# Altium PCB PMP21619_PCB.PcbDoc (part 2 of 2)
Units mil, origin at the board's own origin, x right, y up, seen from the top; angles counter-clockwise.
Board outline 3937.01 x 3937.01 mil, 8 copper layers (Top Layer, Signal Layer 1, Signal Layer 2, Signal Layer 3, Signal Layer 4, Signal Layer 5, Signal Layer 6, Bottom Layer), stack 62.283 mil thick; 227 components, 41 nets, 547 pads, 421 vias.
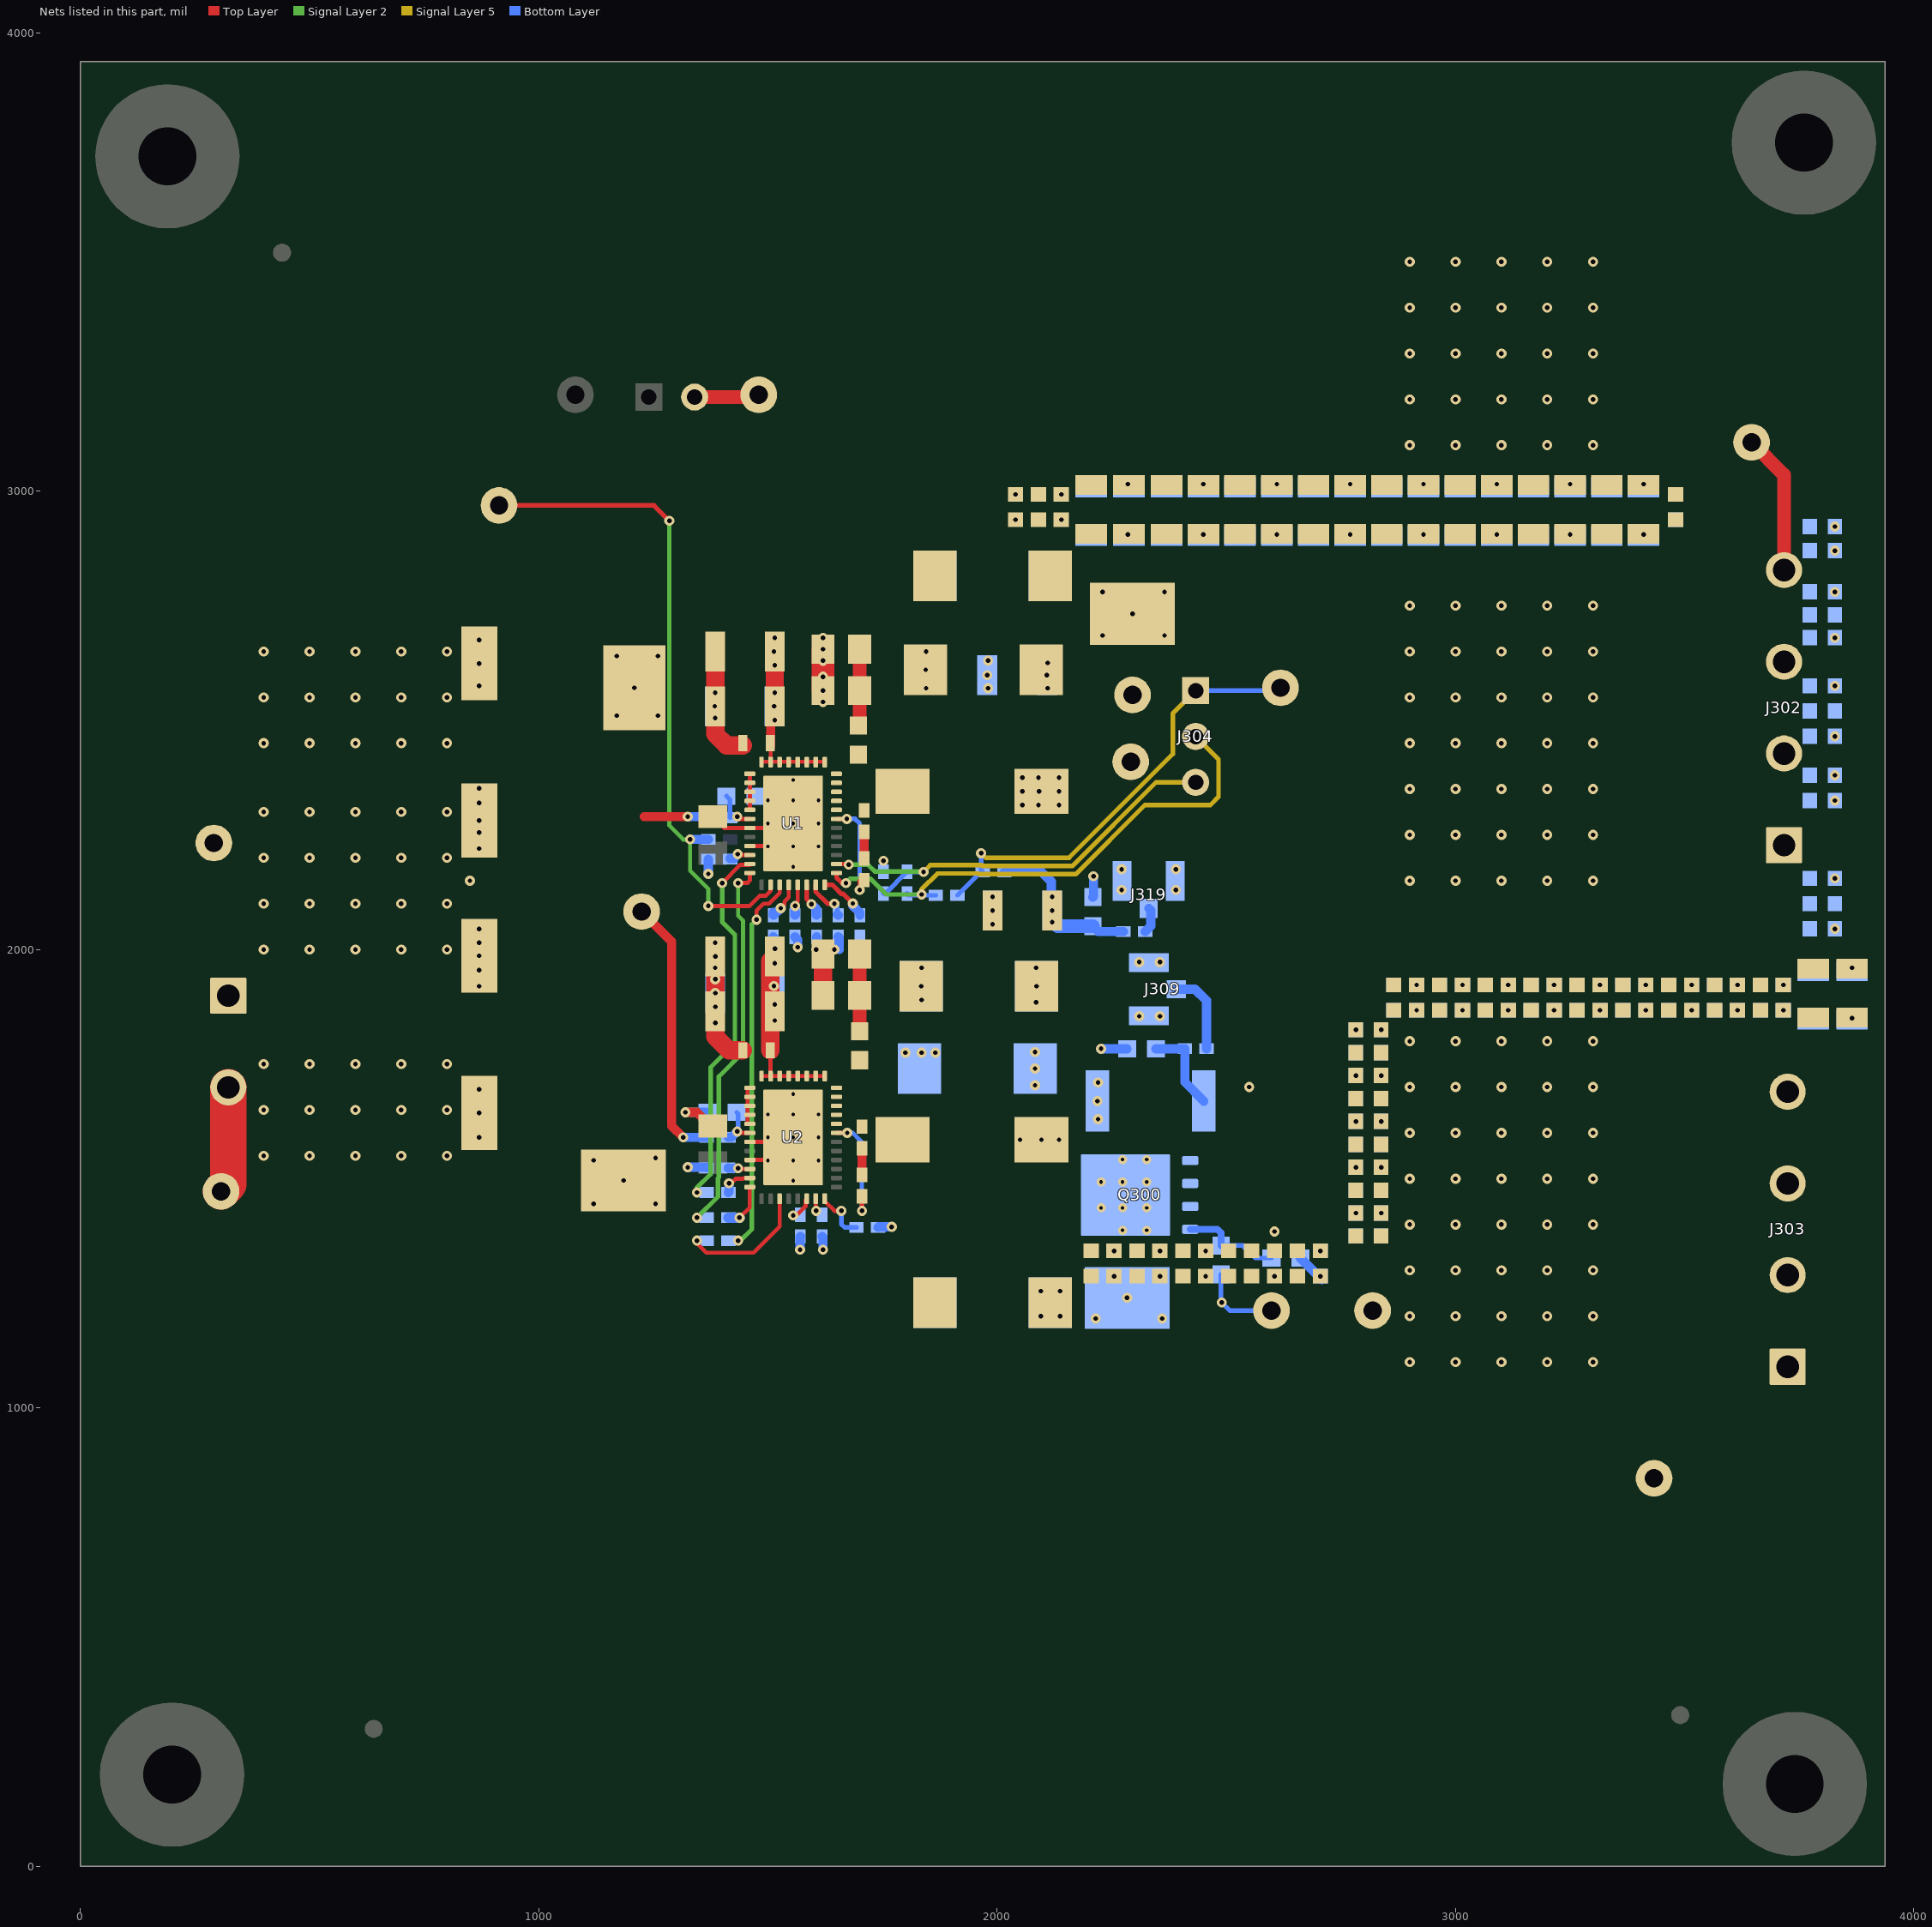
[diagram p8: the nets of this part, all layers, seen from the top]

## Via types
v1: diameter 22, hole 10, Top Layer to Bottom Layer, tented both sides, 317 vias
v2: diameter 22, hole 10, Top Layer to Bottom Layer, 72 vias
v3: diameter 19.68, hole 7.87, Top Layer to Bottom Layer, 32 vias

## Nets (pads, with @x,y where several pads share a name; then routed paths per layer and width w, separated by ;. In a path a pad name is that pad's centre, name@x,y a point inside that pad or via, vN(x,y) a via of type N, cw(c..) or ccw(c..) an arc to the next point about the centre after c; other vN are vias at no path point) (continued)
GND: C10.1 C13.2 C14.1 C15.1 C16.1 C17.1 C20.2 C23.2 C24.2 C25.2 C26.2 C27.2 C50.2 C51.2 C52.2 C53.2 C54.2 C55.2 C56.2 C91.2 C92.2 C93.2 C94.2 C100.2 C101.2 C102.2 C103.2 C104.2 C105.2 C106.2 C107.2 C108.2 C109.2 C110.2 C111.2 C112.2 C113.2 C114.2 C115.2 C116.2 C117.2 C118.2 C119.2 C120.2 C121.2 C122.2 C123.2 C124.2 C125.2 C126.2 C127.2 C128.2 C129.2 C130.2 C131.2 C132.2 C133.2 C134.2 C135.2 C136.2 C137.2 C201.2 C202.2 C203.2 C204.2 C205.2 C206.2 C207.2 C208.2 C209.2 C210.2 C211.2 C212.2 C213.2 C214.2 C215.2 C216.2 C217.2 C218.2 C219.2 C220.2 C221.2 C222.2 C223.2 C224.2 C225.2 C226.2 C227.2 C228.2 C229.2 C230.2 C231.2 C232.2 C233.2 C234.2 C235.2 C236.2 C237.2 C238.2 C239.2 C240.2 C241.2 C242.2 C243.2 C244.2 C245.2 C246.2 C247.2 C248.2 C249.2 C250.2 C251.2 C252.2 C253.2 C254.2 C255.2 C256.2 C257.2 C258.2 C259.2 C260.2 C261.2 C262.2 C263.2 C264.2 C265.2 C266.2 C267.2 C268.2 C269.2 C270.2 C271.2 C272.2 C273.2 C274.2 C275.2 C276.2 C277.2 C278.2 C279.2 C280.2 C281.2 C282.2 C283.2 C284.2 C285.2 C286.2 C300.2 C319.2 J101.2 J300.2 J303.1 J303.2 J303.3 J303.4 J309.2@2330.71,1971.46 J309.3@2330.71,1855.31 J319.2@2388.78,2149.61 J319.3@2272.64,2149.61 R10.1 R11.1 R12.1 R13.2 R14.2 R15.2 R16.1 R17.1 R21.1 R23.1 R24.1 R25.2 R26.1 R27.2 R50.1 R302.1 R303.1 TP109.1 TP303.1 TP304.1 TP305.1 TP307.1 TP308.1 TP309.1 TP315.1 U1.13 U1.14 U1.15 U1.16 U1.17 U1.18 U1.19 U1.20 U1.27 U1.29 U1.41@1555,2275 U2.13 U2.14 U2.15 U2.16 U2.17 U2.18 U2.19 U2.20 U2.27 U2.29 U2.41@1555,1590 | length 2405.9
  Top Layer w9: C10.1@1381.89,2288.03 1404.76,2265.16 U1.27@1460.51,2265.16 U1.41@1545.16,2265.16 ; U2.29@1460.51,1540.79 1505.79,1540.79 U2.41@1545.16,1580.16 ; U2.27@1460.51,1580.16 U2.41@1545.16,1580.16 ; U1.29@1460.51,2225.79 1505.79,2225.79 U1.41@1545.16,2265.16 ; U2.20@1486.1,1723.86 U2.19@1505.79,1723.86 ; U1.20@1486.22,2409.45 U1.19@1505.91,2409.45 ; C27.2@1505,1780 1505.79,1779.21 U2.19@1505.79,1723.86 ; C17.1@1505,2445 1505.91,2444.09 U1.19@1505.91,2409.45 ; v3(1555,1590) U2.41@1545.16,1580.16 ; v3(1555,2275) U1.41@1545.16,2265.16 ; U2.13@1623.9,1723.86 U2.19@1505.79,1723.86 ; U1.13@1624.02,2409.45 U1.19@1505.91,2409.45
  Top Layer w20: v1(1320,1645) 1345,1645 1375,1615 C20.2@1385,1615 ; C17.1@1505.91,2445 C16.1@1505.91,2530
  Top Layer w30: J101.2@1340,3205 1475,3205 TP109.1@1480,3210
  Top Layer w40: C27.2@1505,1780 1505,1975.04 C24.2@1514.96,1985 ; C26.2@1509.84,1874.02 C26.2@1513.78,1870.08 ; C16.1@1514.96,2530 C15.1@1514.96,2650 ; R27.2@1620,1900 R26.1@1620,1990
  Top Layer w50: v1(1620,2565) v1(1620,2655)
  Top Layer w80: TP303.1@307.09,1472.44 322.83,1488.19 J300.2@322.83,1699.21
  Bottom Layer w20: v1(1320,1645) C23.2@1368.5,1645 ; v1(1325,1525) 1364.76,1525 R21.1@1366.14,1523.62 ; v1(1370,2165) 1370,2196.77 R13.2@1370.08,2196.85 ; R14.2@1511.61,2027.56 1515.24,2023.94 v1(1515.24,2001.97) ; R12.1@1558.86,2027.56 1565,2021.42 v1(1565,2005) ; v1(1570,1345) 1570,1373.15 R23.1@1570.87,1374.02 ; v1(1605.24,2000) 1606.1,2000.87 R11.1@1606.1,2027.56 ; R24.1@1618.11,1374.02 1620,1372.13 v1(1620,1345) ; R10.1@1653.35,2027.56 1655.24,2025.67 v1@1655.24,2000 ; R25.2@1740.16,1393.7 1741.46,1395 v1(1770,1395) ; C319.2@2208.66,2114.17 2210,2115.51 v1(2210,2160) ; v1(2226.54,1783.46) C300.2@2283.46,1783.46 ; R302.1@2661.42,1326.77 2708.19,1280 2705,1283.19 v1(2705,1287.44)
  other v1: 2900,1100 3000,1100 3100,1100 3200,1100 3300,1100 2215,1195 2360,1195 2900,1200 3000,1200 3100,1200 3200,1200 3300,1200 2283.46,1240.16 2355,1287.44 2900,1300 3000,1300 3100,1300 3200,1300 3300,1300 2900,1400 3000,1400 3100,1400 3200,1400 3300,1400 1120,1445 1255,1445 1185.04,1496.06 2900,1500 3000,1500 3100,1500 3200,1500 3300,1500 1120,1540 1255,1545 400,1550 500,1550 600,1550 700,1550 800,1550 870,1590 2900,1600 3000,1600 3100,1600 3200,1600 3300,1600 2220,1630 870.08,1643.7 400,1650 500,1650 600,1650 700,1650 800,1650 2218.5,1669.29 870,1695 2900,1700 3000,1700 3100,1700 3200,1700 3300,1700 2220,1710 400,1750 500,1750 600,1750 700,1750 800,1750 1800,1775 1835,1775 1865,1775 2900,1800 3000,1800 3100,1800 3200,1800 3300,1800 1515,1845 2310,1854.33 2355,1854.33 1515,1880 1835,1890 1512.99,1920.12 1834.02,1920 1835,1960 1515,1970 2310,1972.44 2355,1972.44 1645,2000 1990,2055 1990.04,2085 1990,2115 2271.65,2130 2390,2130 2271.65,2175 2389.76,2175 1751.97,2193.67 400,2450 500,2450 600,2450 700,2450 800,2450 1515,2500 1170,2510 1260,2510 1513.78,2530.49 1620,2540 400,2550 500,2550 600,2550 700,2550 800,2550 1514.96,2560 1845,2570 1980,2570 1208.66,2570.87 870,2575 1620,2595 1978.35,2598.43 1844.02,2610 1515,2620 870.08,2624.02 1620,2630 1980,2630 1170,2640 1260,2640 400,2650 500,2650 600,2650 700,2650 800,2650 1512.99,2650 1845,2650 870,2675 1515,2680 1620,2680 2230,2685 2365,2685 2295.28,2732.28 2230,2780 2365,2780 2900,3100 3000,3100 3100,3100 3200,3100 3300,3100 2900,3200 3000,3200 3100,3200 3200,3200 3300,3200 2900,3300 3000,3300 3100,3300 3200,3300 3300,3300 2900,3400 3000,3400 3100,3400 3200,3400 3300,3400 2900,3500 3000,3500 3100,3500 3200,3500 3300,3500
  other v2: 2255,1287.44 2455,1287.44 2605,1287.44 2837.56,1425 2837.56,1525 2837.56,1625 2837.56,1725 2837.56,1825 3865,1850 2915,1867.44 3015,1867.44 3115,1867.44 3215,1867.44 3315,1867.44 3415,1867.44 3515,1867.44 3615,1867.44 3715,1867.44 3827.56,2045 3827.56,2155 3827.56,2325 3827.56,2380 3827.56,2465 3827.56,2575 3827.56,2680 3827.56,2780 3827.56,2870 3827.56,2922.64 2040,2992.56 2140,2992.56 2285,3015 2450,3015 2610,3015 2770,3015 2930,3015 3090,3015 3250,3015 3410,3015
  other v3: 1555,1495.51 1499.88,1539.61 1555,1539.61 1610.12,1539.61 1499.88,1590 1610.12,1590 1499.88,1640.39 1555,1640.39 1610.12,1640.39 1555,1684.49 1555,2180.51 1499.88,2224.61 1555,2224.61 1610.12,2224.61 1499.88,2275 1610.12,2275 1499.88,2325.39 1555,2325.39 1610.12,2325.39 1555,2369.49
NetC11_1: C11.1 C12.2 L1.1 U1.8 U1.9 U1.10 U1.11 U1.12
NetC11_2: C11.2 R16.2 R17.2 | length 168.1
  Top Layer w30: C11.2@1696.85,2488.19 1700,2491.34 R17.2@1700,2565 R16.2@1700,2655
NetC12_1: C12.1 R19.1 | length 57.8
  Top Layer w20: R19.1@1710,2198.62 C12.1@1710,2256.38
NetC13_1: C13.1 R31.2 U1.26 | length 94.8
  Top Layer w9: v1@1435,2285 1435.16,2284.84 U1.26@1460.51,2284.84
  Bottom Layer w10: C13.1@1409.45,2334.65 1417.32,2326.77 R31.2@1417.32,2287.4 1419.92,2290 v1(1433,2290) v1@1435,2290
NetC21_1: C21.1 C22.2 L2.1 U2.8 U2.9 U2.10 U2.11 U2.12
NetC21_2: C21.2 R26.2 R27.1 | length 143.5
  Top Layer w30: C21.2@1700,1821.5 R26.2@1700,1965
NetC22_1: C22.1 R29.1 | length 57.8
  Top Layer w20: R29.1@1705,1508.62 C22.1@1705,1566.38
NetC23_1: C23.1 R41.1 U2.26 | length 100
  Top Layer w9: v1(1433,1603) 1436.16,1599.84 U2.26@1460.51,1599.84
  Bottom Layer w10: C23.1@1431.5,1645 1435,1641.5 v1@1435,1600
  Bottom Layer w20: R41.1@1413.62,1590 1420,1590 v1(1433,1603)
NetC300_1: C300.1 Q300.1 Q300.2 Q300.3 R303.2 R304.1 | length 194.3
  Bottom Layer w20: C300.1@2346.46,1783.46 R304.1@2409.45,1783.46 2409.45,1710.63 R303.2@2450.79,1669.29
NetJ304_1: J304.1 R52.1 R53.2 TP107.1 | length 981
  Signal Layer 5 w10: v1(1965,2210) 1975,2200 2156.66,2200 2383.07,2426.41 2383.07,2514.57 J304.1@2433.07,2564.57
  Bottom Layer w10: R52.1@1913.39,2118.11 1964.57,2169.29 R53.2@1968.5,2169.29 1965,2172.8 v1(1965,2210) ; J304.1@2433.07,2564.57 2611.81,2564.57 TP107.1@2618.11,2570.87
NetJ304_2: J304.2 R51.2 R52.2 U1.1 | length 1179.1
  Top Layer w10: U1.1@1649.49,2166.73 1649.49,2156.81 1661.3,2145 v1(1670,2145)
  Signal Layer 2 w10: v1(1670,2145) 1678.87,2153.87 1690.11,2153.87 1724.08,2153.87 1757.95,2120 v1(1835,2120)
  Signal Layer 5 w10: v1(1835,2120) 1835,2131 1870,2166 1958.44,2166 1960.19,2164.25 2171.47,2164.25 2322.22,2315 2465,2315 2483.07,2333.07 2483.07,2414.57 J304.2@2433.07,2464.57
  Bottom Layer w10: R51.2@1803.15,2122.05 1807.09,2118.11 R52.2@1866.14,2118.11
NetJ304_3: J304.3 R50.2 R51.1 U1.2 | length 979.3
  Top Layer w10: U1.2@1649.49,2186.42 v1@1676,2186.42
  Signal Layer 2 w10: v1(1676,2185) 1718.23,2185 1733.44,2169.8 1838.79,2169.8 v1(1839.29,2169.29) ; J304.3@2427.46,2364.57 J304.3@2433.07,2364.57
  Signal Layer 5 w10: v1(1839.29,2169.29) 1853.87,2183.87 1965.85,2183.87 1967.6,2182.13 2164.07,2182.13 2346.51,2364.57 J304.3@2427.46,2364.57
  Bottom Layer w10: R50.2@1751.97,2122.05 1755.91,2122.05 R51.1@1803.15,2169.29 v1(1839.29,2169.29)
NetJ309_1: J309.1 R304.2 | length 181.2
  Bottom Layer w20: J309.1@2390.75,1913.39 2431.61,1913.39 2456.69,1888.31 R304.2@2456.69,1783.46
NetJ319_1: J319.1 R314.1 | length 57
  Bottom Layer w20: R314.1@2322.83,2039.37 2335,2051.54 2335,2085.28 J319.1@2330.71,2089.57
NetQ300_4: Q300.4 R301.1 R302.2 | length 219.5
  Bottom Layer w10: R301.1@2488.19,1354.33 2535.67,1354.33 2563.23,1326.77 R302.2@2598.43,1326.77
  Bottom Layer w15: Q300.4@2421.06,1389.57 2480.43,1389.57 2488.19,1381.81 R301.1@2488.19,1354.33
NetR10_2: R10.2 U1.39 | length 90.5
  Top Layer w10: U1.39@1604.21,2141.14 1604.21,2125.79 1630,2100 v1@1640,2100
  Bottom Layer w10: v1(1645,2100) 1651.48,2093.52 R10.2@1651.48,2076.67
  Bottom Layer w20: R10.2@1651.48,2076.67 R10.2@1653.35,2074.8
NetR11_2: R11.2 U1.38 | length 81.8
  Top Layer w10: U1.38@1584.53,2141.14 1584.53,2109.65 v1(1595,2099.18)
  Bottom Layer w20: v1(1595,2099.18) 1606.1,2088.08 R11.2@1606.1,2074.8 1605.24,2075.67 R11.2@1605.24,2080.94
NetR12_2: R12.2 U1.37 | length 74.5
  Top Layer w9: v1(1559.12,2095) 1559.12,2099.18 1564.84,2104.9 U1.37@1564.84,2141.14
  Bottom Layer w20: v1@1558.86,2095 R12.2@1558.86,2074.8 1560.24,2076.18 R12.2@1560.24,2080.06
NetR13_1: R13.1 U1.30 | length 57.1
  Top Layer w9: v1@1436.1,2206.1 U1.30@1460.51,2206.1
  Bottom Layer w9: R13.1@1417.32,2196.85 1424.95,2196.85 1426.6,2198.5 v1@1436.1,2208
  Bottom Layer w20: R13.1@1417.32,2198.5 R13.1@1426.6,2198.5
  other v1: 1434,2208
NetR14_1: R14.1 U1.36 | length 86.9
  Top Layer w9: v1(1528,2090) 1535.75,2097.75 1535.75,2104.68 1545.16,2114.09 U1.36@1545.16,2141.14
  Bottom Layer w20: R14.1@1511.61,2080.8 R14.1@1511.61,2074.8 1512.8,2074.8 v1(1528,2090)
NetR15_1: R15.1 U1.40 | length 104.7
  Top Layer w10: U1.40@1623.9,2141.14 1639.88,2141.14 1653.9,2127.13 1654.11,2127.13 1660.11,2121.13 1664.27,2121.13 v1(1685,2100.39)
  Bottom Layer w20: v1(1685,2100.39) 1685,2095.75 R15.1@1700.59,2080.16
NetR19_2: R19.2 U1.7 | length 221
  Top Layer w9: U1.7@1649.49,2284.84 v1@1672.47,2284.84 ; v1(1700,2130) R19.2@1700,2151.38
  Bottom Layer w10: v1@1672.47,2284.84 1690.16,2284.84 1700,2275 v1(1700,2130)
  other v1: 1672,2284.84
NetR21_2: R21.2 U2.30 | length 47.4
  Top Layer w9: v1@1436.1,1521.1 U2.30@1460.51,1521.1
  Bottom Layer w20: R21.2@1413.39,1523.62 1414.01,1523 v1@1436.1,1523
  other v1: 1435,1523
NetR23_2: R23.2 U2.38 | length 52.4
  Top Layer w9: v1(1555,1420) 1561.94,1420 1573.9,1431.96 1582.14,1440.19 1582.14,1453.75 U2.38@1584.53,1456.14
NetR24_2: R24.2 U2.39 | length 26.5
  Top Layer w9: U2.39@1604.21,1456.14 1604.21,1430.79 v1(1605,1430)
NetR25_1: R25.1 U2.40 | length 117.6
  Top Layer w9: U2.40@1623.9,1458.9 U2.40@1623.9,1456.14 1623.9,1451.1 1645,1430 v1(1660,1430)
  Bottom Layer w10: v1(1660,1430) 1660,1401.02 1667.32,1393.7 R25.1@1692.91,1393.7
NetR29_2: R29.2 U2.7 | length 247.2
  Top Layer w9: U2.7@1649.49,1599.84 v1@1668.03,1599.84
  Top Layer w10: R29.2@1700,1461.38 1705,1456.38 v1(1705,1430)
  Bottom Layer w9: v1@1668.03,1599.84 1685.16,1599.84 1700,1585 1705,1580 v1(1705,1430)
  other v1: 1673,1600
NetR30_2: R30.2 TP103.1 U1.34 | length 1472.4
  Top Layer w9: v1(1370,2095) 1460,2095 1465,2100 1481.96,2116.96 1495,2116.96 1505.79,2127.75 U1.34@1505.79,2141.14
  Top Layer w10: TP103.1@913.39,2968.5 1251.5,2968.5 v1(1285,2935)
  Signal Layer 2 w9: v1(1285,2935) 1285,2270 1315,2240 v1(1330,2240) 1330,2171.94 1370,2131.94 v1(1370,2095)
  Bottom Layer w20: v1(1330,2240) 1369.92,2240 R30.2@1370.08,2240.16
NetR55_1: R55.1 U2.31 | length 65.8
  Top Layer w9: v1@1420,1490 1429.63,1499.63 1444.68,1499.63 1446.47,1501.42 U2.31@1460.51,1501.42
  Bottom Layer w20: R55.1@1413.62,1470 1415,1471.38 v1(1415,1490)
NetR55_2: R55.2 U1.31 | length 808.6
  Top Layer w9: v1(1400,2145) 1439.63,2184.63 1460.51,2184.63 U1.31@1460.51,2186.42
  Signal Layer 2 w9: v1@1401.94,2145 v1(1400,2145) v1@1405,2140
  Signal Layer 2 w10: v1(1345,1470) 1345,1480 1375,1510 1375,1742.87 1427.87,1795.75 1427.87,2031.73 1427.13,2032.48 1427.13,2032.87 1400,2060 v1(1400,2145)
NetR56_1: R56.1 U2.32 | length 100.4
  Top Layer w9: v1(1438,1415) 1460,1437 1460,1481.22 U2.32@1460.51,1481.73
  Bottom Layer w22: R56.1@1413.62,1415 v1(1438,1415)
NetR56_2: R56.2 U1.32 | length 820.2
  Top Layer w9: v1(1435,2145) 1455,2145 1460.51,2150.51 U1.32@1460.51,2166.73
  Signal Layer 2 w9: v1(1435,2145) 1435,2073.36 1445.75,2062.61
  Signal Layer 2 w10: v1(1345,1415) 1390.97,1460.97 1390.97,1500.69 1392.87,1502.6 1392.87,1722.87 1445.75,1775.75 1445.75,2062.61
NetR301_2: R301.2 TP310.1 | length 165.2
  Bottom Layer w10: 2488.19,1241.81 R301.2@2488.19,1291.34 ; v1(2490,1230) 2507.4,1212.6 TP310.1@2598.43,1212.6
SYNC1: R54.2 U2.35 | length 278.9
  Top Layer w9: v1(1345,1365) 1345,1359.5 1365.92,1338.58 1468.58,1338.58 1525.47,1395.47 U2.35@1525.47,1456.14
SYNC2: R54.1 U1.35 | length 826.6
  Top Layer w9: v1(1475,2065) 1475,2085 1490.08,2100.08 1501.99,2100.08 1525.47,2123.57 U1.35@1525.47,2141.14
  Signal Layer 2 w10: v1(1435,1365) 1440,1365 1465,1390 1465,1450 1465,2055 v1(1475,2065) v1@1477.17,2062.83
VIN: C14.2 C15.2 C16.2 C17.2 C24.1 C25.1 C26.1 C27.1 C100.1 C101.1 J300.1 R31.1 R41.2 TP300.1 TP301.1 U1.21 U1.22 U1.23 U1.24 U1.25 U2.21 U2.22 U2.23 U2.24 U2.25 | length 1378
  Top Layer w9: U2.25@1455.51,1619.53 U2.21@1455.51,1698.27 ; U1.25@1460.63,2305.12 U1.21@1460.63,2383.86
  Top Layer w20: TP301.1@1224.41,2082.68 1290,2017.09 1290,1885 1290,1615 v1(1315,1590) ; 1230,2290 v1(1325,2290)
  Top Layer w40: v1(1385.04,1985) C26.1@1385.04,1865 1385.04,1809.96 1415,1780 C27.1@1445,1780 ; C15.2@1385.04,2650 C16.2@1385.04,2530 1385.04,2469.96 1410,2445 C17.2@1445,2445
  Bottom Layer w20: v1(1315,1590) R41.2@1366.38,1590 ; v1(1325,2290) 1367.48,2290 R31.1@1370.08,2287.4
  other v1: 1385.04,1840 1385.04,1875 1385.04,1905 870,1920 1385.04,1935 870,1955 1385,1960.12 870.08,1986.22 400,2000 500,2000 600,2000 700,2000 800,2000 870,2015 1385,2015 870,2045 400,2100 500,2100 600,2100 700,2100 800,2100 850,2150 400,2200 500,2200 600,2200 700,2200 800,2200 870,2220 870,2255 870.08,2281.5 400,2300 500,2300 600,2300 700,2300 800,2300 870,2320 870,2351.31 1385,2505 1383.86,2530.49 1385,2560
VOUT: C50.1 C51.1 C52.1 C53.1 C54.1 C55.1 C56.1 C91.1 C92.1 C93.1 C94.1 C102.1 C103.1 C104.1 C105.1 C106.1 C107.1 C108.1 C109.1 C110.1 C111.1 C112.1 C113.1 C114.1 C115.1 C116.1 C117.1 C118.1 C119.1 C120.1 C121.1 C122.1 C123.1 C124.1 C125.1 C126.1 C127.1 C128.1 C129.1 C130.1 C131.1 C132.1 C133.1 C134.1 C135.1 C136.1 C137.1 C201.1 C202.1 C203.1 C204.1 C205.1 C206.1 C207.1 C208.1 C209.1 C210.1 C211.1 C212.1 C213.1 C214.1 C215.1 C216.1 C217.1 C218.1 C219.1 C220.1 C221.1 C222.1 C223.1 C224.1 C225.1 C226.1 C227.1 C228.1 C229.1 C230.1 C231.1 C232.1 C233.1 C234.1 C235.1 C236.1 C237.1 C238.1 C239.1 C240.1 C241.1 C242.1 C243.1 C244.1 C245.1 C246.1 C247.1 C248.1 C249.1 C250.1 C251.1 C252.1 C253.1 C254.1 C255.1 C256.1 C257.1 C258.1 C259.1 C260.1 C261.1 C262.1 C263.1 C264.1 C265.1 C266.1 C267.1 C268.1 C269.1 C270.1 C271.1 C272.1 C273.1 C274.1 C275.1 C276.1 C277.1 C278.1 C279.1 C280.1 C281.1 C282.1 C283.1 C284.1 C285.1 C286.1 C319.1 J302.1 J302.2 J302.3 J302.4 L1.2 L2.2 Q300.5 Q300.6 Q300.7 Q300.8 Q300.9@2280.09,1464.57 R53.1 R314.2 TP105.1 TP106.1 TP302.1 | length 670.2
  Top Layer w30: TP302.1@3645.67,3106.3 3716.54,3035.43 J302.4@3716.54,2827.56
  Bottom Layer w20: R53.1@2015.75,2169.29 2096.69,2169.29 2117.99,2147.99 C54.1@2117.99,2065.32 ; C319.1@2208.66,2051.18 2220.47,2039.37 R314.2@2275.59,2039.37
  Bottom Layer w30: C54.1@2117.99,2065.32 2132.13,2051.18 C319.1@2208.66,2051.18
  other v1: 2050,1585 2096.57,1585 2135,1585 2550,1700 2082.68,1703.85 2082.68,1740.16 2082.68,1776.47 2085,1885 2085.98,1920 2085,1960 2120,2060 2119.96,2085 2120,2115 2900,2150 3000,2150 3100,2150 3200,2150 3300,2150 2900,2250 3000,2250 3100,2250 3200,2250 3300,2250 2055,2315 2090,2315 2135,2315 2055,2345 2091.57,2345 2135,2345 2900,2350 3000,2350 3100,2350 3200,2350 3300,2350 2055,2375 2090,2375 2135,2375 2900,2450 3000,2450 3100,2450 3200,2450 3300,2450 2900,2550 3000,2550 3100,2550 3200,2550 3300,2550 2110,2570 2108.27,2598.43 2110,2625 2900,2650 3000,2650 3100,2650 3200,2650 3300,2650 2900,2750 3000,2750 3100,2750 3200,2750 3300,2750
  other v2: 2095,1200 2137.64,1200 2095,1255 2137.64,1255 2255,1342.56 2355,1342.56 2455,1342.56 2705,1342.56 2605,1385 2782.44,1425 2782.44,1525 2782.44,1625 2782.44,1725 2782.44,1825 2915,1922.56 3015,1922.56 3115,1922.56 3215,1922.56 3315,1922.56 3415,1922.56 3515,1922.56 3615,1922.56 3715,1922.56 3865,1960 2285,2905 2450,2905 2610,2905 2770,2905 2930,2905 3090,2905 3250,2905 3410,2905 2040,2937.44 2140,2937.44
  other v3: 2273.62,1387.4 2326.38,1387.4 2226.77,1436.42 2273.62,1436.42 2326.38,1436.42 2226.77,1492.72 2273.62,1492.72 2326.38,1492.72 2273.62,1541.73 2326.38,1541.73
pads on no net: FID1.1 FID2.1 FID3.1 H1.1 H2.1 H3.1 H4.1 H5.0 H6.0 H7.0 H8.0 J309.2@2330.71,1972.44 J309.3@2330.71,1854.33 J319.2@2389.76,2149.61 J319.3@2271.65,2149.61 LBL1.0 Q300.9@2247.24,1408.27 Q300.9@2247.24,1464.57 Q300.9@2247.24,1520.87 Q300.9@2296.06,1464.57 Q300.9@2300,1408.27 Q300.9@2300,1464.57 Q300.9@2300,1520.87 Q300.9@2352.76,1408.27 Q300.9@2352.76,1464.57 Q300.9@2352.76,1520.87 U1.3 U1.4 U1.5 U1.6 U1.41@1522.91,2199.41 U1.41@1522.91,2249.8 U1.41@1522.91,2300.2 U1.41@1522.91,2350.59 U1.41@1587.09,2199.41 U1.41@1587.09,2249.8 U1.41@1587.09,2300.2 U1.41@1587.09,2350.59 U2.1 U2.2 U2.3 U2.4 U2.5 U2.6 U2.34 U2.36 U2.37 U2.41@1522.91,1514.41 U2.41@1522.91,1564.8 U2.41@1522.91,1615.2 U2.41@1522.91,1665.59 U2.41@1587.09,1514.41 U2.41@1587.09,1564.8 U2.41@1587.09,1615.2 U2.41@1587.09,1665.59

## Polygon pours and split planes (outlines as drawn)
GND on Signal Layer 1 "SIGNAL_LAYER_1_GND_P058" (solid, remove dead copper, pour order 58): 0,0 0,3937.01 3937.01,3937.01 3946.85,3946.85 3946.85,0
GND on Signal Layer 4 "SIGNAL_LAYER_4_GND_P065" (solid, remove dead copper, pour order 65): 0,0 -10,10 -10,3937.01 3937.01,3937.01 3946.85,3946.85 3946.85,0
GND on Signal Layer 6 "SIGNAL_LAYER_6_GND_P070" (solid, remove dead copper, pour order 70): 0,0 -10,10 -10,3937.01 3937.01,3937.01 3946.85,3946.85 3946.85,0
VOUT on Top Layer "TOP_LAYER_VOUT_P076" (solid, pour order 76): 2055,1165 2175,1165 2175,1360 2055,1360
VOUT on Top Layer "TOP_LAYER_VOUT_P056" (solid, remove dead copper, pour order 56): 2800,1324.47 2800,1905 3900,1905 3900,2950 2000,2950 2000,1324.47
VOUT on Top Layer "TOP_LAYER_VOUT_P052" (solid, remove dead copper, pour order 52): 2010,2698.58 2010,1335 2470,1335 2470,2694.96
VOUT on Top Layer "TOP_LAYER_VOUT_P053" (solid, remove dead copper, pour order 53): 2165.35,2095 3946.85,2095 3946.85,2948.15 3945,2950 2165.35,2950
VIN on Top Layer "TOP_LAYER_VIN_P050" (solid, remove dead copper, pour order 50): 90.21,1820 1355,1820 1355,1700 1381.46,1673.54 1421.46,1673.54 1450,1645 1445,1640 1445,1629.02 1470,1629.02 1470,2046 1321,2195 1320,2195 1320,2300 1315,2305 1460.63,2305.12 1460.63,2707.17 1463.46,2710 1365,2710 1365,2456.42 1318.58,2410 89.86,2410
NetC21_1 on Top Layer "TOP_LAYER_NETC21_1_P054" (solid, remove dead copper, pour order 54): 1640,1615 1691.65,1615 1695,1611.65 1693.19,1609.84 1693.19,1600 1735,1600 1735,1535 1855,1535 1850,1540 1850,1785 1680,1785 1680,1765 1640,1725 1640,1625
NetC11_1 on Top Layer "TOP_LAYER_NETC11_1_P055" (solid, remove dead copper, pour order 55): 1640,2300 1690,2300 1690,2285 1850,2285 1850,2445 1675,2445 1640,2410
VIN on Top Layer "TOP_LAYER_VIN_P051" (solid, remove dead copper, pour order 51): 1465,2475.37 1465,2395 1470,2390 1470,2300 1440,2300 1440,2310 1420,2330 1375,2330 1365,2340 1365,2475
GND on Top Layer "TOP_LAYER_GND_P057" (solid, remove dead copper, pour order 57): -20,-10 -20,3946.52 3918.44,3946.52 3928.28,3956.36 3928.28,-10
VOUT on Bottom Layer "BOTTOM_LAYER_VOUT_P078" (solid, pour order 78): 2050,1160 2179.84,1160 2180,1160.16 2180,1355 2055,1355
GND on Bottom Layer "BOTTOM_LAYER_GND_P074" (solid, remove dead copper, pour order 74): -5,0 -5,3956.52 3933.44,3956.52 3943.28,3966.36 3943.28,0
VOUT on Bottom Layer "BOTTOM_LAYER_VOUT_P072" (solid, remove dead copper, pour order 72): 1998.76,2640 1998.76,2216.47 1998.76,2147.64 2031.47,2147.64 2031.47,1670 2185,1670 2185,2640
VIN on Bottom Layer "BOTTOM_LAYER_VIN_P071" (solid, remove dead copper, pour order 71): 90,1820 1354.79,1820 1354.79,1700 1381.24,1673.54 1421.24,1673.54 1449.79,1645 1444.79,1640 1444.79,1629.02 1469.79,1629.02 1469.79,2046 1320.79,2195 1319.79,2195 1319.79,2300 1314.79,2305 1460.42,2305.12 1460.42,2707.17 1463.25,2710 1364.79,2710 1364.79,2456.42 1318.37,2410 89.65,2410
VOUT on Bottom Layer "Bottom Layer-Vout" (solid, pour order 69): 2800,1905 2800,1325 2060,1325 2060,2090 2060,2953.15 3790,2953.15 3790,2000 3911.52,2000 3911.52,1905.96
GND on Signal Layer 3 "SIGNAL_LAYER_3_GND_P064" (solid, remove dead copper, pour order 64): -5,0 -5,3956.52 3933.44,3956.52 3943.28,3966.36 3943.28,0
VIN on Signal Layer 3 "SIGNAL_LAYER_3_VIN_P063" (solid, remove dead copper, pour order 63): 90.21,1820 1355,1820 1355,1700 1381.46,1673.54 1421.46,1673.54 1450,1645 1445,1640 1445,1629.02 1470,1629.02 1470,2046 1321,2195 1320,2195 1320,2300 1315,2305 1460.63,2305.12 1460.63,2707.17 1463.46,2710 1365,2710 1365,2456.42 1318.58,2410 89.86,2410
VOUT on Signal Layer 5 "SIGNAL_LAYER_5_VOUT_P049" (solid, pour order 49): 2055,1165 2175,1165 2175,1355 2055,1355
GND on Signal Layer 5 "SIGNAL_LAYER_5_GND_P068" (solid, remove dead copper, pour order 68): -5,0 -5,3956.52 3933.44,3956.52 3943.28,3966.36 3943.28,0
VOUT on Signal Layer 5 "SIGNAL_LAYER_5_VOUT_P067" (solid, remove dead copper, pour order 67): 2800,1325 2800,1905 3900,1905 3900,2950.53 2000,2950.53 2000,1325
VIN on Signal Layer 5 "SIGNAL_LAYER_5_VIN_P066" (solid, remove dead copper, pour order 66): 90.21,1820 1355,1820 1355,1700 1381.46,1673.54 1421.46,1673.54 1450,1645 1445,1640 1445,1629.02 1470,1629.02 1470,2046 1321,2195 1320,2195 1320,2300 1315,2305 1460.63,2305.12 1460.63,2707.17 1463.46,2710 1365,2710 1365,2456.42 1318.58,2410 89.86,2410
VOUT on Signal Layer 2 "SIGNAL_LAYER_2_VOUT_P048" (solid, pour order 48): 2055,1360 2175,1360 2173.46,1358.46 2173.46,1165 2055,1165
GND on Signal Layer 2 "SIGNAL_LAYER_2_GND_P062" (solid, remove dead copper, pour order 62): -5,0 -5,3956.52 3933.44,3956.52 3943.28,3966.36 3943.28,0
VIN on Signal Layer 2 "SIGNAL_LAYER_2_VIN_P059" (solid, remove dead copper, pour order 59): 90,1820 1354.79,1820 1354.79,1700 1381.24,1673.54 1421.24,1673.54 1449.79,1645 1444.79,1640 1444.79,1629.02 1469.79,1629.02 1469.79,2046 1320.79,2195 1319.79,2195 1319.79,2300 1314.79,2305 1460.42,2305.12 1460.42,2707.17 1463.25,2710 1364.79,2710 1364.79,2456.42 1318.37,2410 89.65,2410
VOUT on Signal Layer 2 "SIGNAL_LAYER_2_VOUT_P060" (solid, remove dead copper, pour order 60): 2800,1325 2800,1905 3900,1905 3900,2950.53 2000,2950.53 2000,1325

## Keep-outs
Keep-Out Layer:
  lines w19.68: -9.84,0 ccw(c0,0) 0,-9.84 ; -9.84,0 ccw(c0,0) 0,-9.84 ; -9.84,0 -9.84,3937.01 ; -9.84,3937.01 cw(c0,3937.01) 0,3946.85 ; -9.84,3937.01 cw(c0,3937.01) 0,3946.85 ; 0,-9.84 3937.01,-9.84 ; 0,3946.85 3937.01,3946.85 ; 3937.01,-9.84 ccw(c3937.01,0) 3946.85,0 ; 3937.01,-9.84 ccw(c3937.01,0) 3946.85,0 ; 3937.01,3946.85 cw(c3937.01,3937.01) 3946.85,3937.01 ; 3937.01,3946.85 cw(c3937.01,3937.01) 3946.85,3937.01 ; 3946.85,0 3946.85,3937.01
  text ".Layer_Name" at 577,-858.49 h60

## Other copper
Top Layer:
  rectangle net NetC11_1: 1640,2305 1680,2443.5
  rectangle net NetC11_1: 1640,2305 1720,2329.21
  rectangle net VIN: 1440,2308 1471,2475
  rectangle net NetC21_1: 1649.49,1620 1715,1645
  rectangle net NetC21_1: 1640,1620 1665,1740
  text ".Layer_Name" at 577,-858.49 h60
Signal Layer 2:
  rectangle net VIN: 1365,1820 1395,2020
  rectangle net GND: 1485,1465 1545,1665
Signal Layer 4:
  rectangle: 0,-275 125,-150
Signal Layer 6:
  rectangle: 0,-275 125,-150
Bottom Layer:
  rectangle net NetC300_1: 2405,1435 2480,1740
  rectangle net VOUT: 2036.02,1680 2135,1990
  text ".Layer_Name" at 577,-858.49 h60

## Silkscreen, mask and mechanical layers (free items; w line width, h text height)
Top Overlay:
  region: 2320,210 2020,210 2020,110 2320,110
  lines w10: 1338.58,1338.58 2165.35,1338.58 2165.35,2716.54 1338.58,2716.54 1338.58,1338.58
  text "Jumper J101 to disable" at 980.32,3393.7 h72.83
  text "Enable" at 1070.87,3322.83 h72.83
  text "Gnd" at 1346.46,3314.96 h72.83
  text "Power Good" at 992.13,2952.76 h72.83
  text "Remote sense Positive /" at 2688.98,2594.49 h72.83
  text "Bode Injection" at 2685.04,2531.5 h72.83
  text "Vout" at 2232.28,2476.38 h72.83 r90
  text "Vout Adjust" at 2520,2435 h72.83
  text "Remote Sense negative" at 2531.5,2338.58 h72.83
  text "Vout" at 2228.35,2330.71 h72.83 r90
  text "Vout - Load" at 3480.31,2295.28 h118.11 r90
  text "VIN" at 1030,2165 h118.11
  text "VIN" at 625.98,1881.89 h118.11 r90
  text "GND" at 606.3,1578.74 h118.11 r90
  text "Load Return" at 3476.38,1090.55 h118.11 r90
  text "Flip board for Dynamic Load Testing & Ripple Measurement" at 334.65,956.69 h118.11
  text "'.PRJ_Number'.PCB_Rev-" at 1422,128.77 h108.27
  text ".Layer_Name" at 577,-858.49 h60
Bottom Overlay:
  lines w10: 2153.54,2716.54 1338.58,2716.54 1338.58,1338.58 1720.47,1338.58 2165.35,1338.58 2165.35,2716.54
  text "Vsense" at 2790,2120 h118.11
  text "Isense" at 2770,1895 h118.11
  text "Signal Gen." at 2705,660 h118.11 r270
  text ".Layer_Name" at 577,-858.49 h60
Top Paste:
  text ".Layer_Name" at 577,-858.49 h60
Bottom Paste:
  text ".Layer_Name" at 577,-858.49 h60
Top Solder:
  text ".Layer_Name" at 577,-858.49 h60
  text ".Layer_Name" at 577,-858.49 h60
Bottom Solder:
  text ".Layer_Name" at 577,-858.49 h60
Drill Guide:
  text ".Layer_Name" at 577,-858.49 h60
M1 Board Outline:
  the board outline again, w10
  text ".Layer_Name" at 577,-858.49 h60
M2 Board Dimensions:
  rectangle: 0,-275 125,-150
  rectangle: 125,-400 500,-275
  lines w7: 0,-275 1000,-275 ; 125,-400 125,-150 ; 250,-400 250,-150 ; 500,-400 500,-150 ; 750,-400 750,-150 ; 0,-400 1000,-400 1000,-150 0,-150 0,-400
  text ".Layer_Name" at 577,-858.49 h60
M3 3D STEP Top:
  text ".Layer_Name" at 577,-858.49 h60
M4 3D STEP Bottom:
  text ".Layer_Name" at 577,-858.49 h60
M5 Assembly Top:
  lines w10: -292,-930.17 6308,-930.17 ; -292,-726.83 6310,-726.83 ; -292,-523.5 -292,-1133.5 3713,-1133.5 6310,-1133.5 6310,-523.5 -291.5,-523.5 -291.5,-1133.5 1284,-1133.5 ; 2173,-1133.5 2173,-523.5 ; 3440,-726.83 3440,-523.5 ; 4280,-726.83 4280,-523.5 ; 4902,-1140 4902,-937.17
  text "COMPONENTS MARKED 'DNP' SHOULD NOT BE POPULATED." at 1153.5,-318.5 h60
  text "ASSEMBLY VARIANT:" at 1153,-434 h60
  text ".VariantName" at 2189,-434 h60
  text "PCB VIEWED FROM TOP SIDE" at -228.5,-655.67 h60
  text "BOARD #:" at 2248,-655.67 h60
  text ".PRJ_Number" at 2793.5,-655.67 h60
  text "REV:" at 3638,-655.67 h60
  text ".PCB_Rev" at 3929.5,-655.67 h60
  text "SVN REV:" at 4476,-655.67 h60
  text ".VersionControl_RevNumber" at 4982,-655.67 h60
  text "TID #:" at 2248,-859 h60
  text ".TID" at 2793.5,-859 h60
  text "PLOT NAME =" at -228.5,-1064.34 h60
  text ".plot_File_Name" at 577,-1064.34 h60
  text "GENERATED    :" at 2250,-1064.34 h60
  text ".Print_Date" at 3119.5,-1064.34 h60
  text ".Print_Time" at 3848.5,-1064.34 h60
  text "TEXAS INSTRUMENTS" at 5113,-1064.34 h60
M6 Assembly Bottom:
  lines w10: -292.5,-727.33 6309.5,-727.33 ; -290.5,-930.67 6309.5,-930.67 ; 1115.5,-1140.5 1115.5,-937.67 ; 1737.5,-727.33 1737.5,-524 ; 2577.5,-727.33 2577.5,-524 ; 3844.5,-1134 3844.5,-524 ; 4733.5,-1134 6309,-1134 6309,-524 -292.5,-524 -292.5,-1134 2304.5,-1134 6309.5,-1134 6309.5,-524
  text "COMPONENTS MARKED 'DNP' SHOULD NOT BE POPULATED." at 6102,-318 h60
  text ".VariantName" at 5058,-434 h60
  text "ASSEMBLY VARIANT:" at 6097,-434 h60
  text ".VersionControl_RevNumber" at 1035.5,-656.17 h60
  text "SVN REV:" at 1541.5,-656.17 h60
  text ".PCB_Rev" at 2088,-656.17 h60
  text "REV:" at 2379.5,-656.17 h60
  text ".PRJ_Number" at 3224,-656.17 h60
  text "BOARD #:" at 3769.5,-656.17 h60
  text "PCB VIEWED FROM BOTTOM SIDE" at 6246,-656.17 h60
  text ".TID" at 3224,-859.5 h60
  text "TID #:" at 3769.5,-859.5 h60
  text "TEXAS INSTRUMENTS" at 904.5,-1064.84 h60
  text ".Print_Time" at 2169,-1064.84 h60
  text ".Print_Date" at 2898,-1064.84 h60
  text "GENERATED    :" at 3767.5,-1064.84 h60
  text ".plot_File_Name" at 5440.5,-1064.84 h60
  text "PLOT NAME =" at 6246,-1064.84 h60
M9 Title Sheet:
  drawing of 57 lines, arcs and shapes, not listed
  text "1" at 739.84,8036.5 h70
  text "2" at 3235.5,8036.5 h70
  text "3" at 5724.84,8036.5 h70
  text "4" at 8231.51,8036.5 h70
  text "5" at 10730.5,8036.5 h70
  text "6" at 13235.5,8036.5 h70
  text "A" at -416.5,6893.5 h70
  text "A" at 14383.5,6893.5 h70
  text "B" at -416.5,4513.5 h70
  text "B" at 14383.5,4513.5 h70
  text "C" at -416.5,2138.5 h70
  text "C" at 14383.5,2138.5 h70
  text "PROJECT TITLE:" at 11343.5,277.5 h45
  text ".PRJ_Title" at 11393.5,144.17 h70
  text "DESIGNED FOR:" at 11343.5,-23.5 h45
  text ".PRJ_Customer" at 11393.5,-163.5 h70
  text "D" at -416.5,-231.5 h70
  text "D" at 14383.5,-231.5 h70
  text "FILE NAME:" at 11343.5,-323.5 h45
  text ".PCB_File_Name_No_Path" at 11393.5,-443.5 h70
  text "Texas Instruments (TI) and/or its licensors do not warrant the accuracy or completeness of this specification" at 6374,-605.34 h45
  text "ENGINEER:" at 11343.5,-613.5 h45
  text "LAYOUT BY:" at 12848.5,-613.5 h45
  text "or any information contained therein. TI and/or its licensors do not warrant that this design will meet" at 6329.01,-718 h45
  text ".PRJ_Engineer" at 11393.5,-768.49 h70
  text ".PCB_Layout" at 12899,-768.49 h70
  text "the specifications, will be suitable for your application or fit for any particular purpose, or will operate in" at 6329.01,-830.67 h45
  text ".Layer_Name" at 577,-858.49 h60
  text "ALTIUM DESIGNER VERSION:" at 12848.5,-923.5 h45
  text "an implementation. TI and/or its licensors do not warrant that the design is production worthy. You should" at 6329.01,-943.33 h45
  text "completely validate and test your design implementation to confirm the system functionality for your application." at 6374,-1056 h45
  text ".print_Scale" at 11393.5,-1056.83 h70
  text ".Application_BuildNumber" at 12899,-1056.83 h70
  text "1" at 739.84,-1263.5 h70
  text "2" at 3235.5,-1263.5 h70
  text "3" at 5724.84,-1263.5 h70
  text "4" at 8231.51,-1263.5 h70
  text "5" at 10730.5,-1263.5 h70
  text "6" at 13235.5,-1263.5 h70
M10 Fab Notes:
  drawing of 173 lines, arcs and shapes, not listed
  text "DESIGN INFORMATION" at 12378.02,6201 h60
  text "MIN. TRACK WIDTH:" at 11733.46,6021 h60
  text "8" at 12829.7,6021 h60
  text "MIL" at 12984.46,6021 h60
  text "MIN. CLEARANCE:" at 11733.46,5889 h60
  text "0.2" at 12769.7,5889 h60
  text "mm" at 12984.46,5889 h60
  text "MIN. VIA PAD SIZE:" at 11733.46,5757 h60
  text "22" at 12799.71,5757 h60
  text "MIL" at 12984.46,5757 h60
  text "0.05mm (2MIL)" at 12428.46,5615.29 h60
  text "MINIMUM ANNULAR RING" at 11404.23,5611 h60
  text "EXTERNAL" at 13136.46,5611 h60
  text "PER" at 11604.23,5493 h60
  text "IPC-D-275 CLASS 2 LEVEL C" at 11824.23,5493 h60
  text "MIL, HOLES" at 13312.46,5380.71 h60
  text "+/-" at 12920,5380 h60
  text "+/-" at 13774,5380 h60
  text "REGISTRATION TOLERANCES:" at 11404.23,5375 h60
  text "METAL" at 12604,5375 h60
  text "5" at 13180.2,5375 h60
  text "3" at 14013.2,5375 h60
  text "MIL" at 14129.46,5375 h60
  text "+/-" at 13774,5262 h60
  text "HOLE SIZE TOLERANCE (UNLESS OTHERWISE SPECIFIED):" at 11404.23,5257 h60
  text "3" at 14013.2,5257 h60
  text "MIL" at 14129.46,5257 h60
  text "MATERIAL:" at 11329.46,5047.54 h60
  text "FR-4 High Tg" at 12315.9,4907.21 h60
  text "FR-408" at 11750.46,4898.64 h60
  text "OTHER" at 13238.46,4898.64 h60
  text "X" at 12161,4895 h60
  text "62 MIL (1.6mm) +/-10%" at 12070.56,4735.92 h60
  text "THICKNESS:" at 11404.23,4731.64 h60
  text "X" at 11942.4,4731.64 h60
  text "OTHER" at 13355.46,4731.64 h60
  text "TOLERANCE:" at 11404.23,4573.64 h60
  text "X" at 12243.53,4573.64 h60
  text "ANSI IPC-6012 TYPE 3 CLASS 2" at 12430.48,4573.64 h60
  text "OTHER +/-" at 12430.46,4417.64 h60
  text "BOW & TWIST:" at 11404.23,4260.64 h60
  text "X" at 12243.53,4260.64 h60
  text "ANSI IPC-6012 TYPE 3 CLASS 2" at 12430.48,4260.64 h60
  text "OTHER +/-" at 12430.46,4102.13 h60
  text "DRILLING:" at 11329.46,3963.64 h60
  text "REFERENCE:" at 11404.23,3846.64 h60
  text "X" at 12052.46,3846.64 h60
  text "AS SHOWN" at 12239.46,3846.64 h60
  text "X" at 12953.46,3846.64 h60
  text "NC_DRILL FILES" at 13090.46,3846.64 h60
  text "PTH COPPER THICKNESS:" at 11404.23,3688.64 h60
  text "X" at 12534.46,3688.64 h60
  text "20-30 um" at 12671.46,3688.64 h60
  text "OTHER" at 13388.46,3688.64 h60
  text "BOARD FINISH:" at 11329.46,3529.64 h60
  text "SILKSCREEN:" at 11484.68,3411.64 h60
  text "X" at 12433.46,3411.64 h60
  text "TOP" at 12559.46,3411.64 h60
  text "X" at 12943.46,3411.64 h60
  text "BOTTOM" at 13070.46,3411.64 h60
  text "SILKSCREEN COLOR:" at 11484.68,3244.64 h60
  text "X" at 12432.42,3244.64 h60
  text "WHITE" at 12559.46,3244.64 h60
  text "OTHER" at 13070.46,3244.64 h60
  text "X" at 12563.42,3085.44 h60
  text "GREEN" at 12690.46,3085.44 h60
  text "OTHER" at 13308.46,3085.44 h60
  text "SOLDER RESIST COLOR:" at 11484.68,3074.64 h60
  text "X" at 12563.42,2915.44 h60
  text "MATTE" at 12690.46,2915.44 h60
  text "SEMI-GLOSS" at 13308,2914.8 h60
  text "IMMERSION GOLD (ENIG)" at 12390.46,2726.92 h60
  text "ENEPIG" at 13728,2723.64 h60
  text "SURFACE FINISH:" at 11329.46,2722.64 h60
  text "X" at 12203.51,2722.64 h60
  text "IMM. TIN/SILVER OR EQUIV" at 11659,2565.64 h60
  text "OTHER" at 13090.46,2565.64 h60
  text "X" at 12205,2390 h60
  text "ARRAY/PANEL:" at 11329.46,2386.64 h60
  text "CUT AND TRIM PER M1 BOARD OUTLINE" at 12390.46,2382.35 h60
  text "N.C. ROUTE" at 12390.46,2230.64 h60
  text "V. SCORE" at 13256.46,2230.64 h60
  text "CERTIFICATION:" at 11329.46,2093.64 h60
  text "MATERIALS AND WORKMANSHIP FOR ALL PCBS" at 12054.46,2093.64 h60
  text "TO MEET OR EXCEED THE REQUIREMENTS OF:" at 12054.46,1995.64 h60
  text "X" at 11680.96,1859.13 h60
  text "ANSI IPC-A-600F CLASS ->" at 11819.96,1859.13 h60
  text "X" at 13459.02,1859.13 h60
  text "2" at 13577.96,1859.14 h60
  text "1" at 13262.96,1857.64 h60
  text "3" at 13931.96,1857.64 h60
  text "X" at 12495.02,1699.64 h60
  text "RoHS" at 12631.96,1699.64 h60
  text "OTHER" at 13276.36,1699.64 h60
  text "PER ORDER" at 13673.42,1699.64 h60
  text "ALL BOARDS MUST MEET OR EXCEED UL94-V0 REQUIREMENTS." at 11357,1534 h60
  text "PCB MUST BEAR THE UL94V-0 UL REGISTERED MATERIAL ID NUMBER" at 11357,1414 h60
  text "ADDITIONAL REQUIREMENTS:" at 11329.46,1240.64 h60
  text "MICROSECTION:" at 11404.23,1125.64 h60
  text "YES" at 12309.96,1125.64 h60
  text "REQUIRED" at 13171.46,969.49 h60
  text "BARE BOARD ELEC. TEST:" at 11404.23,966.64 h60
  text "NONE" at 12709.96,966.64 h60
  text "X" at 13044.46,966.64 h60
  text "PER ORDER" at 13763.46,966.64 h60
  text ".Layer_Name" at 577,-858.49 h60
M11 Gerber Information:
  lines w10: -292,-930.17 6308,-930.17 ; -292,-726.83 6310,-726.83 ; -292,-523.5 -292,-1133.5 3713,-1133.5 6310,-1133.5 6310,-523.5 -291.5,-523.5 -291.5,-1133.5 1284,-1133.5 ; 2173,-1133.5 2173,-523.5 ; 3440,-726.83 3440,-523.5 ; 4280,-726.83 4280,-523.5 ; 4902,-1140 4902,-937.17
  text "ALL ARTWORK VIEWED FROM TOP SIDE" at -228.5,-655.67 h60
  text "BOARD #:" at 2248,-655.67 h60
  text ".PRJ_Number" at 2793.5,-655.67 h60
  text "REV:" at 3638,-655.67 h60
  text ".PCB_Rev" at 3929.5,-655.67 h60
  text "SVN REV:" at 4476,-655.67 h60
  text ".VersionControl_RevNumber" at 4982,-655.67 h60
  text "LAYER NAME =" at -228.5,-858.49 h60
  text "TID #:" at 2248,-859 h60
  text ".TID" at 2793.5,-859 h60
  text "PLOT NAME =" at -228.5,-1064.34 h60
  text ".plot_File_Name" at 577,-1064.34 h60
  text "GENERATED    :" at 2250,-1064.34 h60
  text ".Print_Date" at 3119.5,-1064.34 h60
  text ".Print_Time" at 3848.5,-1064.34 h60
  text "TEXAS INSTRUMENTS" at 5113,-1064.34 h60
M12 Stackup:
  drawing of 503 lines, arcs and shapes, not listed
  text "Layer" at 6217.5,3117.5 h60
  text "Name" at 6627.41,3117.5 h60
  text "Material" at 7567.15,3117.5 h60
  text "Thickness" at 8426.92,3117.5 h60
  text "Constant" at 9076.76,3117.5 h60
  text "Board Layer Stack" at 9646.62,3117.5 h60
  text "1" at 6217.5,2997.5 h60
  text "Top Overlay" at 6627.41,2997.5 h60
  text "2" at 6217.5,2877.5 h60
  text "Top Solder" at 6627.41,2877.5 h60
  text "Solder Resist" at 7567.15,2877.5 h60
  text "0.40mil" at 8426.92,2877.5 h60
  text "3.5" at 9076.76,2877.5 h60
  text "3" at 6217.5,2757.5 h60
  text "Top Layer" at 6627.41,2757.5 h60
  text "Copper" at 7567.15,2757.5 h60
  text "2.09mil" at 8426.92,2757.5 h60
  text "4" at 6217.5,2637.5 h60
  text "Dielectric1" at 6627.41,2637.5 h60
  text "FR-4" at 7567.15,2637.5 h60
  text "5.91mil" at 8426.92,2637.5 h60
  text "4.8" at 9076.76,2637.5 h60
  text "5" at 6217.5,2517.5 h60
  text "Signal Layer 1" at 6627.41,2517.5 h60
  text "Copper" at 7567.15,2517.5 h60
  text "2.79mil" at 8426.92,2517.5 h60
  text "6" at 6217.5,2397.5 h60
  text "Dielectric 2" at 6627.41,2397.5 h60
  text "5.91mil" at 8426.92,2397.5 h60
  text "4.2" at 9076.76,2397.5 h60
  text "7" at 6217.5,2277.5 h60
  text "Signal Layer 2" at 6627.41,2277.5 h60
  text "Copper" at 7567.15,2277.5 h60
  text "2.79mil" at 8426.92,2277.5 h60
  text "8" at 6217.5,2157.5 h60
  text "Dielectric 3" at 6627.41,2157.5 h60
  text "5.91mil" at 8426.92,2157.5 h60
  text "4.2" at 9076.76,2157.5 h60
  text "9" at 6217.5,2037.5 h60
  text "Signal Layer 3" at 6627.41,2037.5 h60
  text "Copper" at 7567.15,2037.5 h60
  text "2.79mil" at 8426.92,2037.5 h60
  text "10" at 6217.5,1917.5 h60
  text "Dielectric 4" at 6627.41,1917.5 h60
  text "5.91mil" at 8426.92,1917.5 h60
  text "4.2" at 9076.76,1917.5 h60
  text "11" at 6217.5,1797.5 h60
  text "Signal Layer 4" at 6627.41,1797.5 h60
  text "Copper" at 7567.15,1797.5 h60
  text "2.79mil" at 8426.92,1797.5 h60
  text "12" at 6217.5,1677.5 h60
  text "Dielectric 5" at 6627.41,1677.5 h60
  text "5.91mil" at 8426.92,1677.5 h60
  text "4.2" at 9076.76,1677.5 h60
  text "13" at 6217.5,1557.5 h60
  text "Signal Layer 5" at 6627.41,1557.5 h60
  text "Copper" at 7567.15,1557.5 h60
  text "2.79mil" at 8426.92,1557.5 h60
  text "14" at 6217.5,1437.5 h60
  text "Dielectric 6" at 6627.41,1437.5 h60
  text "5.91mil" at 8426.92,1437.5 h60
  text "4.2" at 9076.76,1437.5 h60
  text "15" at 6217.5,1317.5 h60
  text "Signal Layer 6" at 6627.41,1317.5 h60
  text "Copper" at 7567.15,1317.5 h60
  text "2.79mil" at 8426.92,1317.5 h60
  text "16" at 6217.5,1197.5 h60
  text "Dielectric 7" at 6627.41,1197.5 h60
  text "5.91mil" at 8426.92,1197.5 h60
  text "4.2" at 9076.76,1197.5 h60
  text "17" at 6217.5,1077.5 h60
  text "Bottom Layer" at 6627.41,1077.5 h60
  text "Copper" at 7567.15,1077.5 h60
  text "2.09mil" at 8426.92,1077.5 h60
  text "18" at 6217.5,957.5 h60
  text "Bottom Solder" at 6627.41,957.5 h60
  text "Solder Resist" at 7567.15,957.5 h60
  text "0.40mil" at 8426.92,957.5 h60
  text "3.5" at 9076.76,957.5 h60
  text "19" at 6217.5,837.5 h60
  text "Bottom Overlay" at 6627.41,837.5 h60
  text ".Layer_Name" at 577,-858.49 h60
M13 Component Bodies Top:
  text ".Layer_Name" at 577,-858.49 h60
M14 Component Bodies Bottom:
  text ".Layer_Name" at 577,-858.49 h60
M15 Courtyards Top:
  text ".Layer_Name" at 577,-858.49 h60
M16 Courtyards Bottom:
  text ".Layer_Name" at 577,-858.49 h60
Drill Drawing:
  circle w10: c568.67,5357.18 r22.05
  lines w10: 546.61,5445.39 557.64,5445.39 568.67,5434.37 579.69,5445.39 590.72,5445.39 579.69,5456.42 590.72,5467.44 579.69,5467.44 568.67,5478.47 557.64,5467.44 546.61,5467.44 557.64,5456.42 546.61,5445.39 ; 546.61,5533.6 590.72,5533.6 590.72,5577.7 546.61,5577.7 546.61,5533.6 ; 546.61,5676.94 590.72,5676.94 568.67,5632.83 546.61,5676.94 ; 546.61,5743.09 557.64,5743.09 557.64,5732.07 579.69,5732.07 579.69,5743.09 590.72,5743.09 590.72,5765.15 579.69,5765.15 579.69,5776.17 557.64,5776.17 557.64,5765.15 546.61,5765.15 546.61,5743.09 ; 546.61,5831.3 568.67,5842.33 590.72,5831.3 579.69,5853.35 590.72,5875.41 568.67,5864.38 546.61,5875.41 557.64,5853.35 546.61,5831.3
  lines w12: 506,5305.36 3612.48,5305.36 ; 506,5900.77 3612.48,5900.77 ; 820.75,5206.13 820.75,6000 ; 1137.19,5206.13 1137.19,6000 ; 1757.43,5206.13 1757.43,6000 ; 2001.15,5206.13 2001.15,6000 ; 2360.6,5206.13 2360.6,6000 ; 3069.58,5206.13 3069.58,6000 ; 506,5206.13 3612.48,5206.13 3612.48,6000 506,6000 506,5206.13
  text "Symbol" at 565.54,5930.54 h72
  text "Quantity" at 850.52,5930.54 h72
  text "Finished Hole Size" at 1166.96,5930.54 h72
  text "Plated" at 1787.2,5930.54 h72
  text "Hole Type" at 2030.92,5930.54 h72
  text "Drill Layer Pair" at 2390.38,5930.54 h72
  text "Hole Tolerance" at 3099.35,5930.54 h72
  text "32" at 850.52,5831.3 h60
  text "7.87mil (0.200mm)" at 1166.96,5831.3 h60
  text "PTH" at 1787.2,5831.3 h60
  text "Round" at 2030.92,5831.3 h60
  text "Top Layer - Bottom Layer" at 2390.38,5831.3 h60
  text "389" at 850.52,5732.07 h60
  text "10.00mil (0.254mm)" at 1166.96,5732.07 h60
  text "PTH" at 1787.2,5732.07 h60
  text "Round" at 2030.92,5732.07 h60
  text "Top Layer - Bottom Layer" at 2390.38,5732.07 h60
  text "5" at 850.52,5632.83 h60
  text "33.47mil (0.850mm)" at 1166.96,5632.83 h60
  text "PTH" at 1787.2,5632.83 h60
  text "Round" at 2030.92,5632.83 h60
  text "Top Layer - Bottom Layer" at 2390.38,5632.83 h60
  text "13" at 850.52,5533.6 h60
  text "40.00mil (1.016mm)" at 1166.96,5533.6 h60
  text "PTH" at 1787.2,5533.6 h60
  text "Round" at 2030.92,5533.6 h60
  text "Top Layer - Bottom Layer" at 2390.38,5533.6 h60
  text "10" at 850.52,5434.37 h60
  text "49.21mil (1.250mm)" at 1166.96,5434.37 h60
  text "PTH" at 1787.2,5434.37 h60
  text "Round" at 2030.92,5434.37 h60
  text "Top Layer - Bottom Layer" at 2390.38,5434.37 h60
  text "4" at 850.52,5335.13 h60
  text "125.98mil (3.200mm)" at 1166.96,5335.13 h60
  text "PTH" at 1787.2,5335.13 h60
  text "Round" at 2030.92,5335.13 h60
  text "Top Layer - Bottom Layer" at 2390.38,5335.13 h60
  text "453 Total" at 850.52,5235.9 h60
  text ".Layer_Name" at 577,-858.49 h60
M17 Embedded Cavity:
  text ".Layer_Name" at 577,-858.49 h60
M18 Embedded Assembly:
  text ".Layer_Name" at 577,-858.49 h60
M19 Embedded Keepout:
  text ".Layer_Name" at 577,-858.49 h60

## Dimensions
0,-400 to 1000,-400 on M2 Board Dimensions
0,0 to 0,3937.01 on M2 Board Dimensions
0,0 to 3937.01,0 on M2 Board Dimensions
